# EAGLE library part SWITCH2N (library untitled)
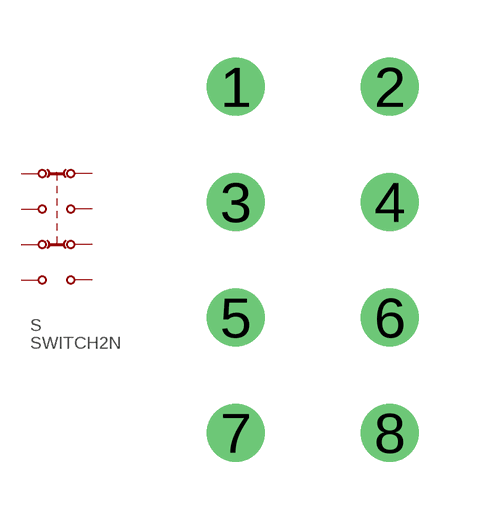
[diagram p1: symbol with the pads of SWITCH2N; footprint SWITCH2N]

Designator prefix S

## SWITCH2N  [SWITCH2N]
1  1  pas
2  2  pas
3  3  pas
4  4  pas
5  5  pas
6  6  pas
7  7  pas
8  8  pas

## Footprint SWITCH2N (pad centres in mm)
drill 1 round: 1 -2,3; 2 2,3; 3 -2,0; 4 2,0; 5 -2,-3; 6 2,-3; 7 -2,-6; 8 2,-6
